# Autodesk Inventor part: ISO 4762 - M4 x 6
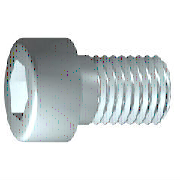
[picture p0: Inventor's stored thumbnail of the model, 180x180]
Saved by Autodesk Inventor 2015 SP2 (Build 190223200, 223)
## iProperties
Created: 2014-02
Part Number: ISO 4762 - M4 x 6
Material: Edelstahl, 440C
Description: Innensechskantschraube
Document SubType Name: Modeling
Standard: ISO 4762
Designer: rYan
Standard Revision: Fourth edition 2004-03-01
Standards Organization: ISO
Language: de-DE
Size Designation: M4 x 6
Categories: <MemberInstance><Categories><Category DisplayName="Verbindungselemente" InternalName="e4da775c-781d-43d5-af7c-5136215cf5a6" Mnemonic="FSTN"><Category DisplayNam
Density: 7.75 g/cm^3
Appearance: Halbpoliert
IsCustomPart: 0
Author: rYan
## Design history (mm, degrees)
sketch "Skizze1"
  geometry: L1 (-1, 0)-(6, 0); L2 (6, 0)-(6, 2); L3 (6, 2)-(1.75, 2); L4 (1.75, 2)-(1.32, 2); L5 (1.32, 2)-(0, 2); L6 (0, 2)-(0, 3.5); L7 (0, 3.5)-(-4, 3.5); L8 (-4, 3.5)-(-4, 1.732); L9 (-4, 1.732)-(-2, 1.732); L10 (-2, 1.732)-(-1, 0); L11 (-6, 0)-(8, 0) reference; L12 (0, -0.7)-(0, 4.2) reference; L13 (1.75, 2)-(0, 2)
  constraints: 22 end point, 6 parallel, 2 collinear, 2 perpendicular, 1 horizontal, 1 point on line
  dimensions: "d1" = 4.25 distance from line of L3.end L2 (= GEL); "d2" = 0.42952 distance of L4.end L3.end (computed from GAL); "d3" = 4 distance between parallel lines of L8 L6 (= KOH); "d4" = 2 distance of L8.end L9.end (= INTI); "d5" = 60 deg angle of L10 L1; "d6" = 4 diameter of L3 L1 (= GD); "d7" = 4 diameter of L5 L1 (= BDM); "d8" = 3.4641 diameter of L9 L1 (= 1.1547 x SW); "d9" = 7 diameter of L7 L1 (= KOD); "d26" = 6 distance between parallel lines of L12 L2 (= NLG)
revolve "Körper" sketch "Skizze1" stored, may be unused: angle "d10" = 90 deg
sketch "Skizze2"
  geometry: L1 (0, -4.9)-(0, 4.9) reference; L2 (-4.9, 0)-(4.9, 0) reference; L3 (1.732, 0)-(0.866, -1.5); L4 (0.866, -1.5)-(-0.866, -1.5); L5 (-0.866, -1.5)-(-1.732, 0); L6 (-1.732, 0)-(-0.866, 1.5); L7 (-0.866, 1.5)-(0.866, 1.5); L8 (0.866, 1.5)-(1.732, 0); 2 further points
  constraints: 12 end point, 1 coincident, 1 horizontal alignment, 1 point on line, 12 other
extrude "Loch" join sketch "Skizze2" stored distance "d11" = 10; taper "d12" = 0 deg
workplane "Work Plane1"
fillet "Fillet2" dims "d30" = 0.1 (= R)
body "Solid1"
fillet "Rundung1" dims "d17" = 0.4 (= RR)
feature "Gewinde" dims "d13" = 4.25 (= GEL), "d14" = 0
chamfer "Fase1" distance "d15" = 0.42941 (= -0.5 x SPD + 0.5 x GD); stored, may be unused: second distance "d16" = 0.42941 (= GUL), angle "d27" = 45 deg
other parameters: "GD" = 4 [user parameter; used in 2 equation terms], "NLG" = 6 [user parameter; used in 1 equation term], "GEL" = 4.25 [user parameter; used in 2 equation terms], "KOD" = 7 [user parameter; used in 1 equation term], "KOH" = 4 [user parameter; used in 1 equation term], "INTI" = 2 [user parameter; used in 1 equation term], "GAL" = 0.42941 (= 0.61345 x PTC) [user parameter; used in 1 equation term], "GUL" = 0.42941 (= 0.61345 x PTC) [user parameter; used in 1 equation term], "BDM" = 4 (= NND) [user parameter; used in 1 equation term], "SW" = 3 [user parameter; used in 2 equation terms], "RR" = 0.4 [user parameter; used in 1 equation term], "SPD" = 3.14117 (= NND - 1.2269 x PTC) [user parameter; used in 1 equation term], "d19" = 0, "d28" = 0, "d29" = 0, "R" = 0.1 [user parameter; used in 1 equation term], "TOA" = 30 deg [user parameter], "GD1" = 3.14117 (= THREADDIA - 1.2269 x PTC) [user parameter], "THREADDIA" = 4 [user parameter; used in 1 equation term], "FAWI" = 45 deg [user parameter], "TPU" = 14.28571 (computed from PTC) [user parameter], "PTC" = 0.7 [user parameter; used in 5 equation terms], "NND" = 4 [user parameter; used in 2 equation terms], "E0" = 3.465 (= 1.155 x SW) [user parameter]
